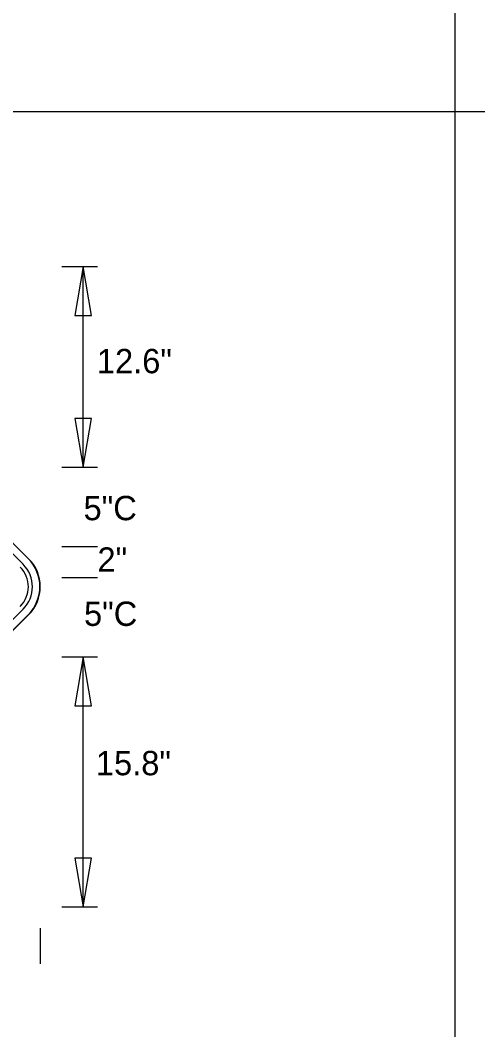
# Model space of a CAD drawing. Extents: x 0 to 770, y 0 to 495.
# Drawn here: x 130 to 195.7, y 198 to 343.1 of the extents above; entities that cross this region are included whole.
import ezdxf

# ---------------------------------------------------------------- set-up
doc = ezdxf.new("R2010")
doc.units = 0
for name, color, linetype in [('Dimension', 7, 'Continuous'), ('GSBWFill', 7, 'Continuous'), ('GSColorFill', 7, 'Continuous'), ('GSDims', 7, 'Continuous'), ('GSOutline', 7, 'Continuous'), ('SheetLines_dp', 7, 'Continuous'), ('TextStructures', 7, 'Continuous')]:
    doc.layers.add(name, color=color, linetype=linetype)

msp = doc.modelspace()

# ---------------------------------------------------------------- linework, layer by layer
at = {"layer": 'Dimension'}
for points in [[(139.07, 307.71), (137.89, 300.69), (140.26, 300.69)], [(139.07, 278.87), (140.26, 285.88), (137.89, 285.88)], [(139.07, 251.61), (137.89, 244.59), (140.26, 244.59)], [(139.07, 215.7), (140.26, 222.71), (137.89, 222.71)]]:
    msp.add_lwpolyline(points, close=True, dxfattribs=at)
at = {"layer": 'GSBWFill'}
for p, q in [((130.44, 264.93), (90.14, 305.23)), ((131.25, 265.73), (90.94, 306.04)), ((90.14, 218.18), (130.44, 258.48)), ((90.94, 217.37), (131.25, 257.67))]:
    msp.add_line(p, q, dxfattribs=at)
for radius in [5.7, 3.99, 4.56]:
    msp.add_arc((127.22, 261.7), radius, 315, 45, dxfattribs=at)
at = {"layer": 'GSColorFill'}
for p, q in [((130.44, 264.93), (90.14, 305.23)), ((90.9, 306), (131.21, 265.69)), ((131.25, 265.73), (90.94, 306.04)), ((131.25, 265.73), (90.94, 306.04)), ((90.14, 218.18), (130.44, 258.48)), ((131.21, 257.71), (90.9, 217.41)), ((90.94, 217.37), (131.25, 257.67)), ((90.94, 217.37), (131.25, 257.67))]:
    msp.add_line(p, q, dxfattribs=at)
for radius in [5.64, 5.7, 5.7, 3.99, 4.56]:
    msp.add_arc((127.22, 261.7), radius, 315, 45, dxfattribs=at)
at = {"layer": 'GSDims'}
for p, q in [((136, 307.71), (141.13, 307.71)), ((139.07, 278.87), (139.07, 307.71)), ((136, 278.87), (141.13, 278.87)), ((136, 278.87), (141.13, 278.87)), ((136, 267.47), (141.13, 267.47)), ((136, 267.47), (141.13, 267.47)), ((136, 263.01), (141.13, 263.01)), ((136, 263.01), (141.13, 263.01)), ((136, 251.61), (141.13, 251.61)), ((136, 251.61), (141.13, 251.61)), ((139.07, 215.7), (139.07, 251.61)), ((136, 215.7), (141.13, 215.7)), ((132.92, 212.62), (132.92, 207.49))]:
    msp.add_line(p, q, dxfattribs=at)
at = {"layer": 'GSOutline'}
for p, q in [((130.44, 264.93), (90.14, 305.23)), ((131.25, 265.73), (90.94, 306.04)), ((90.14, 218.17), (130.44, 258.48)), ((90.94, 217.37), (131.25, 257.67))]:
    msp.add_line(p, q, dxfattribs=at)
for radius in [5.7, 3.99, 4.56]:
    msp.add_arc((127.22, 261.7), radius, 315, 45, dxfattribs=at)
at = {"layer": 'SheetLines_dp'}
for p, q in [((192.5, 0), (192.5, 495)), ((0, 330), (770, 330))]:
    msp.add_line(p, q, dxfattribs=at)

# ---------------------------------------------------------------- texts
at = {"layer": 'TextStructures'}
for s, p in [('12.6"', (141.05, 292.38)), ('5"C', (139.13, 271.26)), ('2"', (141.13, 263.86)), ('5"C', (139.2, 256.07)), ('15.8"', (140.91, 234.61))]:
    msp.add_text(s, height=3.5, dxfattribs=at).set_placement(p)

doc.saveas('drawing.dxf')
